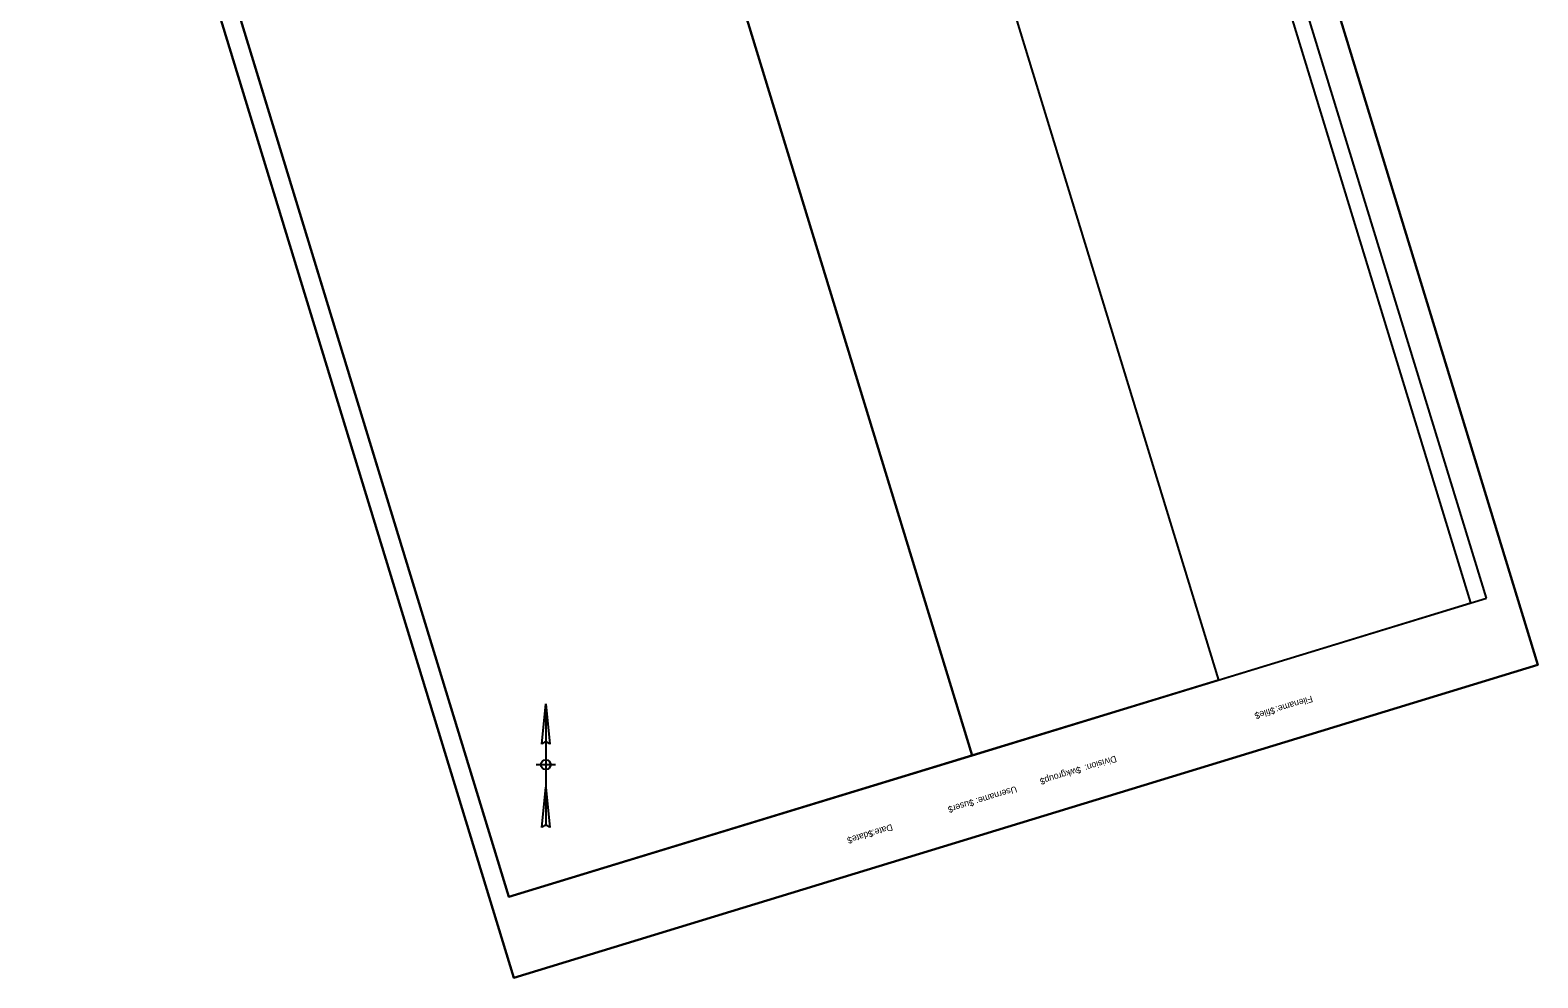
# Model space of a CAD drawing. Extents: x 1037210 to 1037985, y 781657 to 782630.
# Drawn here: x 1037210 to 1037985, y 781657 to 782143 of the extents above; entities that cross this region are included whole.
import ezdxf

# ---------------------------------------------------------------- set-up
doc = ezdxf.new("R2010")
doc.units = 0
for name, color, linetype in [('CLIPS', 7, 'Continuous'), ('Default', 7, 'Continuous'), ('PLOT BOUNDARY', 7, 'Continuous')]:
    doc.layers.add(name, color=color, linetype=linetype)

msp = doc.modelspace()

# ---------------------------------------------------------------- linework, layer by layer
at = {"layer": 'CLIPS'}
for points in [[(1037950.14, 781849.24), (1037730.86, 782566.47), (1037474.57, 782488.12), (1037693.85, 781770.89)], [(1037455.99, 781698.17), (1037236.71, 782415.4), (1037601.14, 782526.81), (1037820.42, 781809.59)], [(1037693.85, 781770.89), (1037474.57, 782488.12), (1037236.71, 782415.4), (1037455.99, 781698.17)]]:
    msp.add_lwpolyline(points, close=True, dxfattribs=at)
at = {"layer": 'Default'}
for p, q in [((1037958.05, 781851.66), (1037724.15, 782616.71)), ((1037222.09, 782463.21), (1037455.99, 781698.17)), ((1037455.99, 781698.17), (1037958.05, 781851.66)), ((1037472.82, 781776.59), (1037474.91, 781797.42)), ((1037474.91, 781797.42), (1037474.91, 781734.92)), ((1037474.91, 781797.42), (1037476.99, 781776.59)), ((1037469.91, 781766.17), (1037479.91, 781766.17)), ((1037472.82, 781733.8), (1037474.91, 781754.64)), ((1037474.91, 781754.64), (1037476.99, 781733.8))]:
    msp.add_line(p, q, dxfattribs=at)
msp.add_lwpolyline([(1037984.51, 781817.44), (1037735.99, 782630.3), (1037210.02, 782469.49), (1037458.54, 781656.63)], close=True, dxfattribs=at)
msp.add_circle((1037474.91, 781766.17), 2.5, dxfattribs=at)
for centre in [(1037474.91, 781775.21), (1037474.91, 781732.42)]:
    msp.add_arc(centre, 2.5, 33.55731, 146.44269, dxfattribs=at)
at = {"layer": 'PLOT BOUNDARY'}
msp.add_lwpolyline([(1037458.54, 781656.63), (1037210.02, 782469.49), (1037735.99, 782630.3), (1037984.51, 781817.44)], close=True, dxfattribs=at)

# ---------------------------------------------------------------- texts
at = {"layer": 'Default'}
for s, p in [('Filename:', (1037868.26, 781801.65)), ('$file$', (1037849, 781795.76)), ('Division:', (1037767.52, 781770.85)), ('$wkgroup$', (1037749.33, 781765.29)), ('Username:', (1037716.35, 781755.21)), ('$user$', (1037694.24, 781748.45)), ('$date$', (1037642.54, 781732.64)), ('Date:', (1037652.52, 781735.69))]:
    msp.add_text(s, height=3.348, rotation=197, dxfattribs=at).set_placement(p)

doc.saveas('drawing.dxf')
